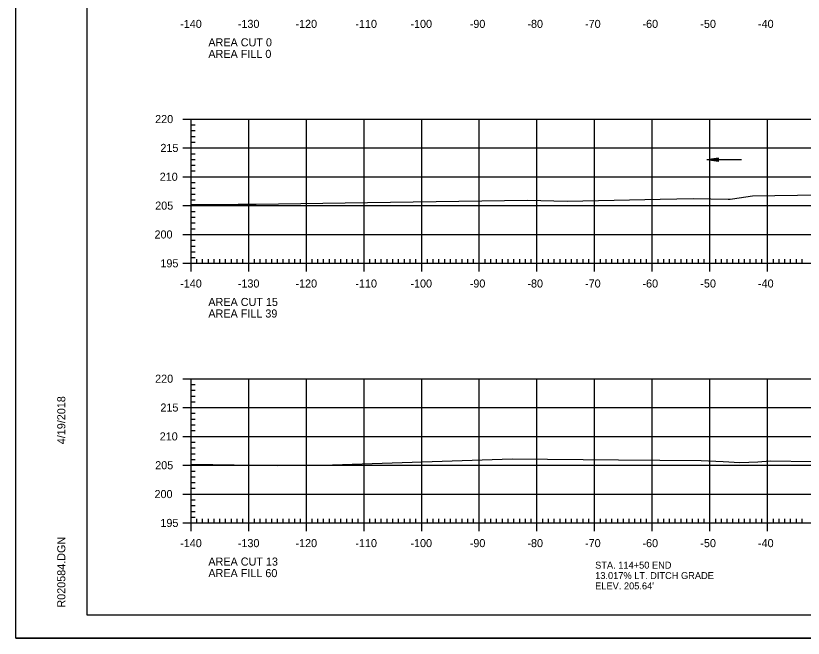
# Model space of a CAD drawing. Extents: x 1312042 to 1371461, y 379929 to 1834241.
# Drawn here: x 1371127.9 to 1371264.5, y 380142.3 to 380250.2 of the extents above; entities that cross this region are included whole.
import ezdxf

# ---------------------------------------------------------------- set-up
doc = ezdxf.new("R2010")
doc.units = 0
for name, color, linetype in [('R_Axis', 7, 'Continuous'), ('R_Axis Annot', 7, 'Continuous'), ('R_Border', 7, 'Continuous'), ('R_Drive', 7, 'Continuous'), ('R_Exist Surface', 7, 'Continuous'), ('R_Grid', 7, 'Continuous'), ('R_No Plot', 7, 'Continuous'), ('R_Water Annot', 7, 'Continuous')]:
    doc.layers.add(name, color=color, linetype=linetype)

msp = doc.modelspace()

# ---------------------------------------------------------------- linework, layer by layer
at = {"layer": 'R_Axis'}
for p, q in [((1371156.88, 380232.25), (1371159.68, 380232.25)), ((1371158.28, 380207.25), (1371158.28, 380232.25)), ((1371158.28, 380231.25), (1371158.98, 380231.25)), ((1371158.28, 380230.25), (1371158.98, 380230.25)), ((1371158.28, 380229.25), (1371158.98, 380229.25)), ((1371158.28, 380228.25), (1371158.98, 380228.25)), ((1371156.88, 380227.25), (1371159.68, 380227.25)), ((1371158.28, 380226.25), (1371158.98, 380226.25)), ((1371158.28, 380225.25), (1371158.98, 380225.25)), ((1371158.28, 380224.25), (1371158.98, 380224.25)), ((1371158.28, 380223.25), (1371158.98, 380223.25)), ((1371156.88, 380222.25), (1371159.68, 380222.25)), ((1371158.28, 380221.25), (1371158.98, 380221.25)), ((1371158.28, 380220.25), (1371158.98, 380220.25)), ((1371158.28, 380219.25), (1371158.98, 380219.25)), ((1371158.28, 380218.25), (1371158.98, 380218.25)), ((1371156.88, 380217.25), (1371159.68, 380217.25)), ((1371158.28, 380216.25), (1371158.98, 380216.25)), ((1371158.28, 380215.25), (1371158.98, 380215.25)), ((1371158.28, 380214.25), (1371158.98, 380214.25)), ((1371158.28, 380213.25), (1371158.98, 380213.25)), ((1371156.88, 380212.25), (1371159.68, 380212.25)), ((1371158.28, 380211.25), (1371158.98, 380211.25)), ((1371158.28, 380210.25), (1371158.98, 380210.25)), ((1371158.28, 380209.25), (1371158.98, 380209.25)), ((1371158.28, 380205.85), (1371158.28, 380208.65)), ((1371158.28, 380208.25), (1371158.98, 380208.25)), ((1371168.28, 380205.85), (1371168.28, 380208.65)), ((1371178.28, 380205.85), (1371178.28, 380208.65)), ((1371188.28, 380205.85), (1371188.28, 380208.65)), ((1371198.28, 380205.85), (1371198.28, 380208.65)), ((1371208.28, 380205.85), (1371208.28, 380208.65)), ((1371218.28, 380205.85), (1371218.28, 380208.65)), ((1371228.28, 380205.85), (1371228.28, 380208.65)), ((1371238.28, 380205.85), (1371238.28, 380208.65)), ((1371248.28, 380205.85), (1371248.28, 380208.65)), ((1371258.28, 380205.85), (1371258.28, 380208.65)), ((1371156.88, 380207.25), (1371159.68, 380207.25)), ((1371158.28, 380207.25), (1371438.28, 380207.25)), ((1371159.28, 380207.25), (1371159.28, 380207.95)), ((1371160.28, 380207.25), (1371160.28, 380207.95)), ((1371161.28, 380207.25), (1371161.28, 380207.95)), ((1371162.28, 380207.25), (1371162.28, 380207.95)), ((1371163.28, 380207.25), (1371163.28, 380207.95)), ((1371164.28, 380207.25), (1371164.28, 380207.95)), ((1371165.28, 380207.25), (1371165.28, 380207.95)), ((1371166.28, 380207.25), (1371166.28, 380207.95)), ((1371167.28, 380207.25), (1371167.28, 380207.95)), ((1371169.28, 380207.25), (1371169.28, 380207.95)), ((1371170.28, 380207.25), (1371170.28, 380207.95)), ((1371171.28, 380207.25), (1371171.28, 380207.95)), ((1371172.28, 380207.25), (1371172.28, 380207.95)), ((1371173.28, 380207.25), (1371173.28, 380207.95)), ((1371174.28, 380207.25), (1371174.28, 380207.95)), ((1371175.28, 380207.25), (1371175.28, 380207.95)), ((1371176.28, 380207.25), (1371176.28, 380207.95)), ((1371177.28, 380207.25), (1371177.28, 380207.95)), ((1371179.28, 380207.25), (1371179.28, 380207.95)), ((1371180.28, 380207.25), (1371180.28, 380207.95)), ((1371181.28, 380207.25), (1371181.28, 380207.95)), ((1371182.28, 380207.25), (1371182.28, 380207.95)), ((1371183.28, 380207.25), (1371183.28, 380207.95)), ((1371184.28, 380207.25), (1371184.28, 380207.95)), ((1371185.28, 380207.25), (1371185.28, 380207.95)), ((1371186.28, 380207.25), (1371186.28, 380207.95)), ((1371187.28, 380207.25), (1371187.28, 380207.95)), ((1371189.28, 380207.25), (1371189.28, 380207.95)), ((1371190.28, 380207.25), (1371190.28, 380207.95)), ((1371191.28, 380207.25), (1371191.28, 380207.95)), ((1371192.28, 380207.25), (1371192.28, 380207.95)), ((1371193.28, 380207.25), (1371193.28, 380207.95)), ((1371194.28, 380207.25), (1371194.28, 380207.95)), ((1371195.28, 380207.25), (1371195.28, 380207.95)), ((1371196.28, 380207.25), (1371196.28, 380207.95)), ((1371197.28, 380207.25), (1371197.28, 380207.95)), ((1371199.28, 380207.25), (1371199.28, 380207.95)), ((1371200.28, 380207.25), (1371200.28, 380207.95)), ((1371201.28, 380207.25), (1371201.28, 380207.95)), ((1371202.28, 380207.25), (1371202.28, 380207.95)), ((1371203.28, 380207.25), (1371203.28, 380207.95)), ((1371204.28, 380207.25), (1371204.28, 380207.95)), ((1371205.28, 380207.25), (1371205.28, 380207.95)), ((1371206.28, 380207.25), (1371206.28, 380207.95)), ((1371207.28, 380207.25), (1371207.28, 380207.95)), ((1371209.28, 380207.25), (1371209.28, 380207.95)), ((1371210.28, 380207.25), (1371210.28, 380207.95)), ((1371211.28, 380207.25), (1371211.28, 380207.95)), ((1371212.28, 380207.25), (1371212.28, 380207.95)), ((1371213.28, 380207.25), (1371213.28, 380207.95)), ((1371214.28, 380207.25), (1371214.28, 380207.95)), ((1371215.28, 380207.25), (1371215.28, 380207.95)), ((1371216.28, 380207.25), (1371216.28, 380207.95)), ((1371217.28, 380207.25), (1371217.28, 380207.95)), ((1371219.28, 380207.25), (1371219.28, 380207.95)), ((1371220.28, 380207.25), (1371220.28, 380207.95)), ((1371221.28, 380207.25), (1371221.28, 380207.95)), ((1371222.28, 380207.25), (1371222.28, 380207.95)), ((1371223.28, 380207.25), (1371223.28, 380207.95)), ((1371224.28, 380207.25), (1371224.28, 380207.95)), ((1371225.28, 380207.25), (1371225.28, 380207.95)), ((1371226.28, 380207.25), (1371226.28, 380207.95)), ((1371227.28, 380207.25), (1371227.28, 380207.95)), ((1371229.28, 380207.25), (1371229.28, 380207.95)), ((1371230.28, 380207.25), (1371230.28, 380207.95)), ((1371231.28, 380207.25), (1371231.28, 380207.95)), ((1371232.28, 380207.25), (1371232.28, 380207.95)), ((1371233.28, 380207.25), (1371233.28, 380207.95)), ((1371234.28, 380207.25), (1371234.28, 380207.95)), ((1371235.28, 380207.25), (1371235.28, 380207.95)), ((1371236.28, 380207.25), (1371236.28, 380207.95)), ((1371237.28, 380207.25), (1371237.28, 380207.95)), ((1371239.28, 380207.25), (1371239.28, 380207.95)), ((1371240.28, 380207.25), (1371240.28, 380207.95)), ((1371241.28, 380207.25), (1371241.28, 380207.95)), ((1371242.28, 380207.25), (1371242.28, 380207.95)), ((1371243.28, 380207.25), (1371243.28, 380207.95)), ((1371244.28, 380207.25), (1371244.28, 380207.95)), ((1371245.28, 380207.25), (1371245.28, 380207.95)), ((1371246.28, 380207.25), (1371246.28, 380207.95)), ((1371247.28, 380207.25), (1371247.28, 380207.95)), ((1371249.28, 380207.25), (1371249.28, 380207.95)), ((1371250.28, 380207.25), (1371250.28, 380207.95)), ((1371251.28, 380207.25), (1371251.28, 380207.95)), ((1371252.28, 380207.25), (1371252.28, 380207.95)), ((1371253.28, 380207.25), (1371253.28, 380207.95)), ((1371254.28, 380207.25), (1371254.28, 380207.95)), ((1371255.28, 380207.25), (1371255.28, 380207.95)), ((1371256.28, 380207.25), (1371256.28, 380207.95)), ((1371257.28, 380207.25), (1371257.28, 380207.95)), ((1371259.28, 380207.25), (1371259.28, 380207.95)), ((1371260.28, 380207.25), (1371260.28, 380207.95)), ((1371261.28, 380207.25), (1371261.28, 380207.95)), ((1371262.28, 380207.25), (1371262.28, 380207.95)), ((1371263.28, 380207.25), (1371263.28, 380207.95)), ((1371264.28, 380207.25), (1371264.28, 380207.95)), ((1371156.88, 380187.25), (1371159.68, 380187.25)), ((1371158.28, 380162.25), (1371158.28, 380187.25)), ((1371158.28, 380186.25), (1371158.98, 380186.25)), ((1371158.28, 380185.25), (1371158.98, 380185.25)), ((1371158.28, 380184.25), (1371158.98, 380184.25)), ((1371156.88, 380182.25), (1371159.68, 380182.25)), ((1371158.28, 380183.25), (1371158.98, 380183.25)), ((1371158.28, 380181.25), (1371158.98, 380181.25)), ((1371158.28, 380180.25), (1371158.98, 380180.25)), ((1371158.28, 380179.25), (1371158.98, 380179.25)), ((1371158.28, 380178.25), (1371158.98, 380178.25)), ((1371156.88, 380177.25), (1371159.68, 380177.25)), ((1371158.28, 380176.25), (1371158.98, 380176.25)), ((1371158.28, 380175.25), (1371158.98, 380175.25)), ((1371158.28, 380174.25), (1371158.98, 380174.25)), ((1371158.28, 380173.25), (1371158.98, 380173.25)), ((1371156.88, 380172.25), (1371159.68, 380172.25)), ((1371158.28, 380171.25), (1371158.98, 380171.25)), ((1371158.28, 380170.25), (1371158.98, 380170.25)), ((1371158.28, 380169.25), (1371158.98, 380169.25)), ((1371156.88, 380167.25), (1371159.68, 380167.25)), ((1371158.28, 380168.25), (1371158.98, 380168.25)), ((1371158.28, 380166.25), (1371158.98, 380166.25)), ((1371158.28, 380165.25), (1371158.98, 380165.25)), ((1371158.28, 380164.25), (1371158.98, 380164.25)), ((1371158.28, 380160.85), (1371158.28, 380163.65)), ((1371158.28, 380163.25), (1371158.98, 380163.25)), ((1371168.28, 380160.85), (1371168.28, 380163.65)), ((1371178.28, 380160.85), (1371178.28, 380163.65)), ((1371188.28, 380160.85), (1371188.28, 380163.65)), ((1371198.28, 380160.85), (1371198.28, 380163.65)), ((1371208.28, 380160.85), (1371208.28, 380163.65)), ((1371218.28, 380160.85), (1371218.28, 380163.65)), ((1371228.28, 380160.85), (1371228.28, 380163.65)), ((1371238.28, 380160.85), (1371238.28, 380163.65)), ((1371248.28, 380160.85), (1371248.28, 380163.65)), ((1371258.28, 380160.85), (1371258.28, 380163.65)), ((1371156.88, 380162.25), (1371159.68, 380162.25)), ((1371158.28, 380162.25), (1371438.28, 380162.25)), ((1371159.28, 380162.25), (1371159.28, 380162.95)), ((1371160.28, 380162.25), (1371160.28, 380162.95)), ((1371161.28, 380162.25), (1371161.28, 380162.95)), ((1371162.28, 380162.25), (1371162.28, 380162.95)), ((1371163.28, 380162.25), (1371163.28, 380162.95)), ((1371164.28, 380162.25), (1371164.28, 380162.95)), ((1371165.28, 380162.25), (1371165.28, 380162.95)), ((1371166.28, 380162.25), (1371166.28, 380162.95)), ((1371167.28, 380162.25), (1371167.28, 380162.95)), ((1371169.28, 380162.25), (1371169.28, 380162.95)), ((1371170.28, 380162.25), (1371170.28, 380162.95)), ((1371171.28, 380162.25), (1371171.28, 380162.95)), ((1371172.28, 380162.25), (1371172.28, 380162.95)), ((1371173.28, 380162.25), (1371173.28, 380162.95)), ((1371174.28, 380162.25), (1371174.28, 380162.95)), ((1371175.28, 380162.25), (1371175.28, 380162.95)), ((1371176.28, 380162.25), (1371176.28, 380162.95)), ((1371177.28, 380162.25), (1371177.28, 380162.95)), ((1371179.28, 380162.25), (1371179.28, 380162.95)), ((1371180.28, 380162.25), (1371180.28, 380162.95)), ((1371181.28, 380162.25), (1371181.28, 380162.95)), ((1371182.28, 380162.25), (1371182.28, 380162.95)), ((1371183.28, 380162.25), (1371183.28, 380162.95)), ((1371184.28, 380162.25), (1371184.28, 380162.95)), ((1371185.28, 380162.25), (1371185.28, 380162.95)), ((1371186.28, 380162.25), (1371186.28, 380162.95)), ((1371187.28, 380162.25), (1371187.28, 380162.95)), ((1371189.28, 380162.25), (1371189.28, 380162.95)), ((1371190.28, 380162.25), (1371190.28, 380162.95)), ((1371191.28, 380162.25), (1371191.28, 380162.95)), ((1371192.28, 380162.25), (1371192.28, 380162.95)), ((1371193.28, 380162.25), (1371193.28, 380162.95)), ((1371194.28, 380162.25), (1371194.28, 380162.95)), ((1371195.28, 380162.25), (1371195.28, 380162.95)), ((1371196.28, 380162.25), (1371196.28, 380162.95)), ((1371197.28, 380162.25), (1371197.28, 380162.95)), ((1371199.28, 380162.25), (1371199.28, 380162.95)), ((1371200.28, 380162.25), (1371200.28, 380162.95)), ((1371201.28, 380162.25), (1371201.28, 380162.95)), ((1371202.28, 380162.25), (1371202.28, 380162.95)), ((1371203.28, 380162.25), (1371203.28, 380162.95)), ((1371204.28, 380162.25), (1371204.28, 380162.95)), ((1371205.28, 380162.25), (1371205.28, 380162.95)), ((1371206.28, 380162.25), (1371206.28, 380162.95)), ((1371207.28, 380162.25), (1371207.28, 380162.95)), ((1371209.28, 380162.25), (1371209.28, 380162.95)), ((1371210.28, 380162.25), (1371210.28, 380162.95)), ((1371211.28, 380162.25), (1371211.28, 380162.95)), ((1371212.28, 380162.25), (1371212.28, 380162.95)), ((1371213.28, 380162.25), (1371213.28, 380162.95)), ((1371214.28, 380162.25), (1371214.28, 380162.95)), ((1371215.28, 380162.25), (1371215.28, 380162.95)), ((1371216.28, 380162.25), (1371216.28, 380162.95)), ((1371217.28, 380162.25), (1371217.28, 380162.95)), ((1371219.28, 380162.25), (1371219.28, 380162.95)), ((1371220.28, 380162.25), (1371220.28, 380162.95)), ((1371221.28, 380162.25), (1371221.28, 380162.95)), ((1371222.28, 380162.25), (1371222.28, 380162.95)), ((1371223.28, 380162.25), (1371223.28, 380162.95)), ((1371224.28, 380162.25), (1371224.28, 380162.95)), ((1371225.28, 380162.25), (1371225.28, 380162.95)), ((1371226.28, 380162.25), (1371226.28, 380162.95)), ((1371227.28, 380162.25), (1371227.28, 380162.95)), ((1371229.28, 380162.25), (1371229.28, 380162.95)), ((1371230.28, 380162.25), (1371230.28, 380162.95)), ((1371231.28, 380162.25), (1371231.28, 380162.95)), ((1371232.28, 380162.25), (1371232.28, 380162.95)), ((1371233.28, 380162.25), (1371233.28, 380162.95)), ((1371234.28, 380162.25), (1371234.28, 380162.95)), ((1371235.28, 380162.25), (1371235.28, 380162.95)), ((1371236.28, 380162.25), (1371236.28, 380162.95)), ((1371237.28, 380162.25), (1371237.28, 380162.95)), ((1371239.28, 380162.25), (1371239.28, 380162.95)), ((1371240.28, 380162.25), (1371240.28, 380162.95)), ((1371241.28, 380162.25), (1371241.28, 380162.95)), ((1371242.28, 380162.25), (1371242.28, 380162.95)), ((1371243.28, 380162.25), (1371243.28, 380162.95)), ((1371244.28, 380162.25), (1371244.28, 380162.95)), ((1371245.28, 380162.25), (1371245.28, 380162.95)), ((1371246.28, 380162.25), (1371246.28, 380162.95)), ((1371247.28, 380162.25), (1371247.28, 380162.95)), ((1371249.28, 380162.25), (1371249.28, 380162.95)), ((1371250.28, 380162.25), (1371250.28, 380162.95)), ((1371251.28, 380162.25), (1371251.28, 380162.95)), ((1371252.28, 380162.25), (1371252.28, 380162.95)), ((1371253.28, 380162.25), (1371253.28, 380162.95)), ((1371254.28, 380162.25), (1371254.28, 380162.95)), ((1371255.28, 380162.25), (1371255.28, 380162.95)), ((1371256.28, 380162.25), (1371256.28, 380162.95)), ((1371257.28, 380162.25), (1371257.28, 380162.95)), ((1371259.28, 380162.25), (1371259.28, 380162.95)), ((1371260.28, 380162.25), (1371260.28, 380162.95)), ((1371261.28, 380162.25), (1371261.28, 380162.95)), ((1371262.28, 380162.25), (1371262.28, 380162.95)), ((1371263.28, 380162.25), (1371263.28, 380162.95)), ((1371264.28, 380162.25), (1371264.28, 380162.95))]:
    msp.add_line(p, q, dxfattribs=at)
at = {"layer": 'R_Border'}
for p, q in [((1371140.28, 380146.25), (1371140.28, 380351.71)), ((1371140.28, 380146.25), (1371140.28, 380146.25)), ((1371456.46, 380146.25), (1371140.28, 380146.25))]:
    msp.add_line(p, q, dxfattribs=at)
at = {"layer": 'R_Exist Surface'}
for points in [[(1371158.28, 380217.43), (1371166.47, 380217.5), (1371169.6, 380217.53), (1371188.87, 380217.77), (1371216.63, 380218.18), (1371223.53, 380218.05), (1371231.66, 380218.22), (1371239.66, 380218.37), (1371245.41, 380218.51), (1371251.45, 380218.37), (1371251.81, 380218.34), (1371252.18, 380218.41), (1371255.66, 380218.96), (1371267.37, 380219.11)], [(1371158.28, 380172.46), (1371173.25, 380172.21), (1371182.79, 380172.31), (1371186.24, 380172.43), (1371214, 380173.35), (1371232.4, 380173.19), (1371246.77, 380173.08), (1371250.56, 380172.92), (1371253.49, 380172.7), (1371256.59, 380172.86), (1371258.75, 380173), (1371265.98, 380172.87)]]:
    msp.add_lwpolyline(points, dxfattribs=at)
at = {"layer": 'R_Grid'}
for p, q in [((1371158.28, 380232.25), (1371438.28, 380232.25)), ((1371158.28, 380207.25), (1371158.28, 380232.25)), ((1371168.28, 380207.25), (1371168.28, 380232.25)), ((1371178.28, 380207.25), (1371178.28, 380232.25)), ((1371188.28, 380207.25), (1371188.28, 380232.25)), ((1371198.28, 380207.25), (1371198.28, 380232.25)), ((1371208.28, 380207.25), (1371208.28, 380232.25)), ((1371218.28, 380207.25), (1371218.28, 380232.25)), ((1371228.28, 380207.25), (1371228.28, 380232.25)), ((1371238.28, 380207.25), (1371238.28, 380232.25)), ((1371248.28, 380207.25), (1371248.28, 380232.25)), ((1371258.28, 380207.25), (1371258.28, 380232.25)), ((1371158.28, 380227.25), (1371438.28, 380227.25)), ((1371158.28, 380222.25), (1371438.28, 380222.25)), ((1371158.28, 380217.25), (1371438.28, 380217.25)), ((1371158.28, 380212.25), (1371438.28, 380212.25)), ((1371158.28, 380207.25), (1371438.28, 380207.25)), ((1371158.28, 380187.25), (1371438.28, 380187.25)), ((1371158.28, 380162.25), (1371158.28, 380187.25)), ((1371168.28, 380162.25), (1371168.28, 380187.25)), ((1371178.28, 380162.25), (1371178.28, 380187.25)), ((1371188.28, 380162.25), (1371188.28, 380187.25)), ((1371198.28, 380162.25), (1371198.28, 380187.25)), ((1371208.28, 380162.25), (1371208.28, 380187.25)), ((1371218.28, 380162.25), (1371218.28, 380187.25)), ((1371228.28, 380162.25), (1371228.28, 380187.25)), ((1371238.28, 380162.25), (1371238.28, 380187.25)), ((1371248.28, 380162.25), (1371248.28, 380187.25)), ((1371258.28, 380162.25), (1371258.28, 380187.25)), ((1371158.28, 380182.25), (1371438.28, 380182.25)), ((1371158.28, 380177.25), (1371438.28, 380177.25)), ((1371158.28, 380172.25), (1371438.28, 380172.25)), ((1371158.28, 380167.25), (1371438.28, 380167.25)), ((1371158.28, 380162.25), (1371438.28, 380162.25))]:
    msp.add_line(p, q, dxfattribs=at)
at = {"layer": 'R_No Plot'}
msp.add_line((1371127.88, 380142.27), (1371461.21, 380142.27), dxfattribs=at)
for points in [[(1371127.87, 380355.6), (1371461.21, 380355.6), (1371461.21, 380142.26), (1371127.87, 380142.26)], [(1371374.2, 380351.71), (1371374.2, 380341.83), (1371409.93, 380341.83), (1371409.93, 380338.91), (1371433.13, 380338.91), (1371433.13, 380314.57), (1371456.46, 380314.57), (1371456.46, 380146.25), (1371140.28, 380146.25), (1371140.28, 380351.71)]]:
    msp.add_lwpolyline(points, close=True, dxfattribs=at)
at = {"layer": 'R_Water Annot'}
for p, q in [((1371249.77, 380225.48), (1371247.77, 380225.18)), ((1371253.77, 380225.18), (1371247.77, 380225.18)), ((1371249.77, 380224.88), (1371247.77, 380225.18)), ((1371249.77, 380225.43), (1371248.1, 380225.18)), ((1371249.77, 380224.93), (1371248.1, 380225.18)), ((1371249.77, 380225.38), (1371248.45, 380225.18)), ((1371249.77, 380224.98), (1371248.45, 380225.18)), ((1371249.77, 380225.33), (1371248.78, 380225.18)), ((1371249.77, 380225.03), (1371248.78, 380225.18)), ((1371249.77, 380225.28), (1371249.12, 380225.18)), ((1371249.77, 380225.08), (1371249.12, 380225.18)), ((1371249.77, 380225.23), (1371249.45, 380225.18)), ((1371249.77, 380225.13), (1371249.45, 380225.18)), ((1371249.77, 380224.88), (1371249.77, 380225.48))]:
    msp.add_line(p, q, dxfattribs=at)

# ---------------------------------------------------------------- texts
at = {"layer": 'R_Axis Annot'}
for s, p in [('-140', (1371156.39, 380248.05)), ('-130', (1371166.39, 380248.05)), ('-120', (1371176.39, 380248.05)), ('-110', (1371186.78, 380248.05)), ('-100', (1371196.33, 380248.05)), ('-90', (1371206.62, 380248.05)), ('-80', (1371216.62, 380248.05)), ('-70', (1371226.62, 380248.05)), ('-60', (1371236.58, 380248.05)), ('-50', (1371246.62, 380248.05)), ('-40', (1371256.62, 380248.05)), ('AREA CUT 0', (1371161.28, 380244.85)), ('AREA FILL 0', (1371161.28, 380242.85)), ('220', (1371152.05, 380231.55)), ('215', (1371152.96, 380226.55)), ('210', (1371152.84, 380221.55)), ('205', (1371152.06, 380216.55)), ('200', (1371151.94, 380211.55)), ('195', (1371152.96, 380206.55)), ('-140', (1371156.39, 380203.05)), ('-130', (1371166.39, 380203.05)), ('-120', (1371176.39, 380203.05)), ('-110', (1371186.78, 380203.05)), ('-100', (1371196.33, 380203.05)), ('-90', (1371206.62, 380203.05)), ('-80', (1371216.62, 380203.05)), ('-70', (1371226.62, 380203.05)), ('-60', (1371236.58, 380203.05)), ('-50', (1371246.62, 380203.05)), ('-40', (1371256.62, 380203.05)), ('AREA CUT 15', (1371161.28, 380199.85)), ('AREA FILL 39', (1371161.28, 380197.85)), ('220', (1371152.05, 380186.55)), ('215', (1371152.96, 380181.55)), ('210', (1371152.84, 380176.55)), ('205', (1371152.06, 380171.55)), ('200', (1371151.94, 380166.55)), ('195', (1371152.96, 380161.55)), ('-140', (1371156.39, 380158.05)), ('-130', (1371166.39, 380158.05)), ('-120', (1371176.39, 380158.05)), ('-110', (1371186.78, 380158.05)), ('-100', (1371196.33, 380158.05)), ('-90', (1371206.62, 380158.05)), ('-80', (1371216.62, 380158.05)), ('-70', (1371226.62, 380158.05)), ('-60', (1371236.58, 380158.05)), ('-50', (1371246.62, 380158.05)), ('-40', (1371256.62, 380158.05)), ('AREA CUT 13', (1371161.28, 380154.85)), ('AREA FILL 60', (1371161.28, 380152.85))]:
    msp.add_text(s, height=1.4, dxfattribs=at).set_placement(p)
at = {"layer": 'R_Border'}
for s, p in [('4/19/2018', (1371136.47, 380175.89)), ('R020584.DGN', (1371136.47, 380147.57))]:
    msp.add_text(s, height=1.4, rotation=90, dxfattribs=at).set_placement(p)
at = {"layer": 'R_Drive'}
for s, p in [('STA. 114+50 END', (1371228.37, 380154.33)), ('13.017% LT. DITCH GRADE', (1371228.37, 380152.53)), ("ELEV. 205.64'", (1371228.37, 380150.73))]:
    msp.add_text(s, height=1.2, dxfattribs=at).set_placement(p)

doc.saveas('drawing.dxf')
